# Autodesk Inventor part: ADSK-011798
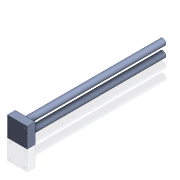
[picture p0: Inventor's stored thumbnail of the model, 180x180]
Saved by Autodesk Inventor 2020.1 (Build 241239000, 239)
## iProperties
Created: 2000-01
Part Number: ADSK-011798
Material: RA Stainless Steel
Document SubType Name: Modeling
Designer: cmcgourin
Density: 8.03 g/cm^3
Appearance: Metal-Stainless Steel
Mass: 1513.98 g
Surface Area: 450.988 cm^2
Volume: 188.541 cm^3
Control State: 0
Checked Out: False
Master: False
Shininess: 0.0
Length Units: 11269
Angle Units: 11279
Time Units: 11290
Mass Units: 11283
Length Display Precision: 3
Angle Display Precision: 2
Compacted: True
Dimensions: 50x50x368,3 mm
Mass: 1,514 kg
DocNumber: ADSK-011798.ipt
Folder: 01 - Themengebiete\Simplification\01 - Packaging machine\
VDS_Category: 3D Komponenten
Density: 0.0
Volumn: 0.0
Area: 0.0
PropertySet Name: Model Information
Author: cmcgourin
Revision Number: -
Title: cylinder
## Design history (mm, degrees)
node "Solide1"
  node "Extrusion1" dims "d0" = 368.3, "d1" = 0
  node "Extrusion2" dims "d4" = 20, "d5" = 0
  node "Hole1" dims "d10" = 4.917, "d11" = 9.525, "d12" = 6.35, "d13" = 60 deg, "d14" = 17.1, "d15" = 118 deg, "d24" = 12
sketch "Sketch1"
  geometry: L1 (0, 13.5)-(0, -13.5); C1 r 8 at (0, 13.5); C2 r 8 at (0, -13.5); 2 further points
  constraints: 2 centre point, 2 end point, 1 coincident, 1 midpoint, 1 vertical, 1 vertical alignment
  dimensions: "d17" = 16 diameter of C1; "d18" = 16 diameter of C2; "d19" = 27 distance of L1.end L1.start
sketch "Sketch2"
  geometry: L1 (0, 0.14)-(0, -26.86); L2 (-25, -38.36)-(25, -38.36); L3 (25, -38.36)-(25, 11.64); L4 (25, 11.64)-(-25, 11.64); L5 (-25, 11.64)-(-25, -38.36); L6 (-25, -38.36)-(25, 11.64); L7 (25, -38.36)-(-25, 11.64); C1 r 8 at (0, 0.14) reference; C2 r 8 at (0, -26.86) reference; 1 further point
  constraints: 14 end point, 3 midpoint, 2 parallel, 1 horizontal, 1 perpendicular, 1 vertical
  dimensions: "d20" = 50 distance of L4.end L3.end; "d21" = 50 distance of L3.end L2.end
sketch "Sketch3"
  geometry: L1 (-18, 18)-(18, 18); L2 (18, 18)-(18, -18); L3 (18, -18)-(-18, -18); L4 (-18, -18)-(-18, 18); L5 (-25, 25)-(-25, -25) reference; L6 (25, 25)-(-25, 25) reference; 6 further points
  constraints: 8 end point, 4 midpoint, 3 horizontal alignment, 3 vertical alignment, 2 parallel, 1 horizontal, 1 perpendicular
  dimensions: "d22" = 36 distance of L1.start L1.end; "d23" = 36 distance of L3.end L1.start (= d22)
node "Corps solides"
node "Corps surfaciques"
